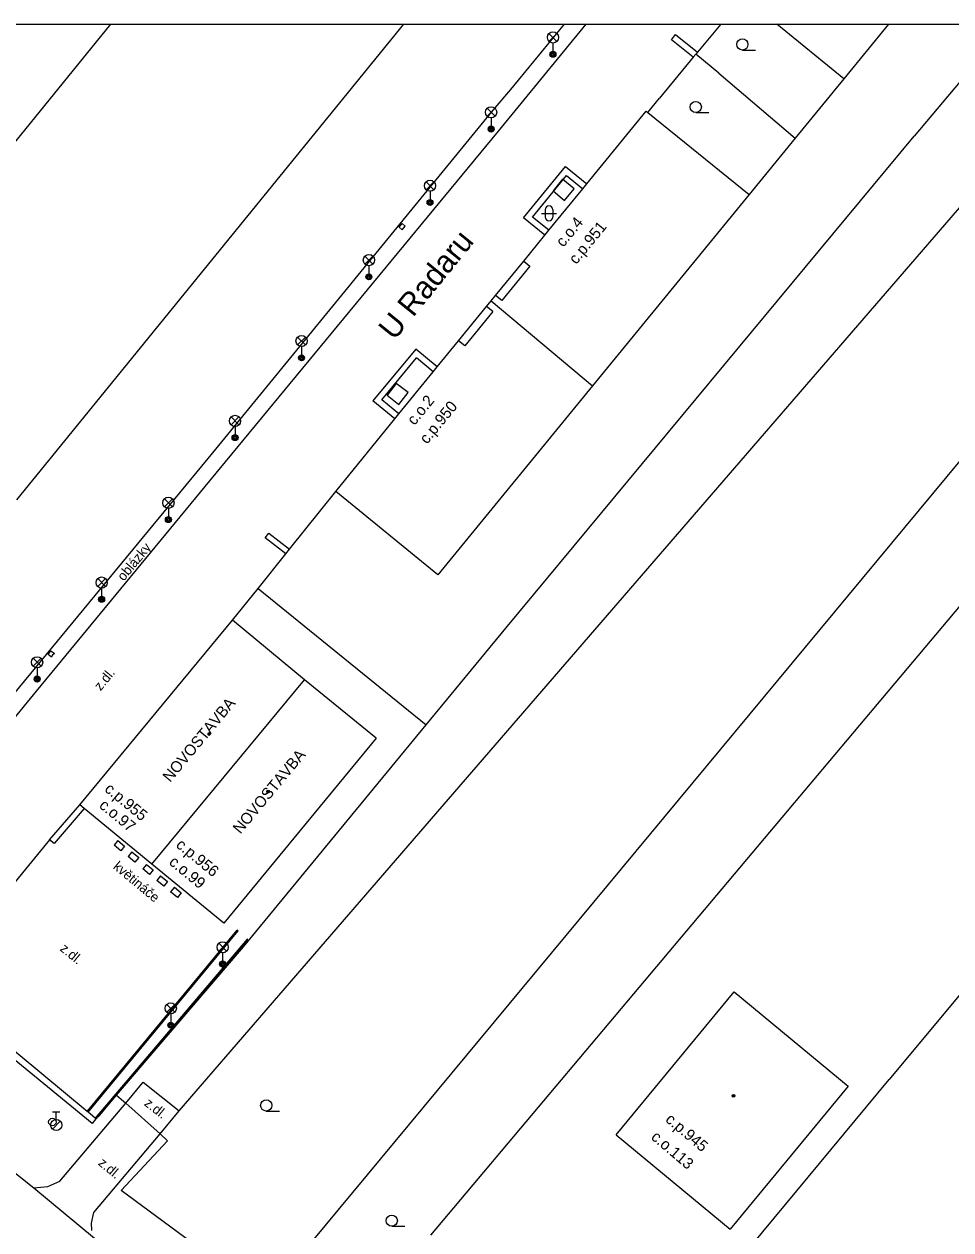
# Model space of a CAD drawing. Extents: x -594386 to -594050, y -1167541 to -1167175.
# Drawn here: x -594325.8 to -594263.8, y -1167256.2 to -1167175.4 of the extents above; entities that cross this region are included whole.
import ezdxf

# ---------------------------------------------------------------- set-up
doc = ezdxf.new("R2010")
doc.units = 0
for name, color, linetype in [('Level 24', 7, 'Continuous'), ('Level 25', 7, 'Continuous'), ('Level 26', 7, 'Continuous'), ('Level 28', 7, 'Continuous'), ('Level 33', 7, 'Continuous'), ('Level 36', 7, 'Continuous'), ('Level 39', 7, 'Continuous'), ('Level 41', 7, 'Continuous'), ('Vrstva 10', 7, 'Continuous'), ('Vrstva 11', 7, 'Continuous'), ('Vrstva 40', 7, 'Continuous'), ('Vrstva 42', 7, 'Continuous'), ('Vrstva 46', 7, 'Continuous'), ('Vrstva 5', 7, 'Continuous'), ('Vrstva 50', 7, 'Continuous'), ('Vrstva 51', 7, 'Continuous'), ('Vrstva 63', 7, 'Continuous'), ('Vrstva 7', 7, 'Continuous'), ('Vrstva 8', 7, 'Continuous')]:
    doc.layers.add(name, color=color, linetype=linetype)

msp = doc.modelspace()

# ---------------------------------------------------------------- linework, layer by layer
at = {"layer": 'Level 24'}
for points in [[(-594300.55, -1167189.2), (-594300.75, -1167189.02), (-594300.55, -1167188.79), (-594300.35, -1167188.97)], [(-594300.55, -1167189.2), (-594300.44, -1167189.07), (-594300.35, -1167188.97)], [(-594324.23, -1167217.65), (-594324.05, -1167217.41)], [(-594324.05, -1167217.41), (-594323.81, -1167217.58), (-594323.96, -1167217.72), (-594324.02, -1167217.83), (-594324.23, -1167217.65)]]:
    msp.add_lwpolyline(points, dxfattribs=at)
at = {"layer": 'Level 25'}
for points in [[(-594319.58, -1167230.12), (-594319.83, -1167230.43)], [(-594319.58, -1167230.12), (-594319.12, -1167230.5)], [(-594319.37, -1167230.81), (-594319.83, -1167230.43)], [(-594319.12, -1167230.5), (-594319.37, -1167230.81)], [(-594318.64, -1167230.88), (-594318.89, -1167231.19)], [(-594318.64, -1167230.88), (-594318.18, -1167231.26)], [(-594318.43, -1167231.57), (-594318.89, -1167231.19)], [(-594318.18, -1167231.26), (-594318.43, -1167231.57)], [(-594317.65, -1167231.71), (-594317.9, -1167232.02)], [(-594317.65, -1167231.71), (-594317.2, -1167232.08)], [(-594317.45, -1167232.39), (-594317.9, -1167232.02)], [(-594317.2, -1167232.08), (-594317.45, -1167232.39)], [(-594316.71, -1167232.49), (-594316.96, -1167232.8)], [(-594316.71, -1167232.49), (-594316.25, -1167232.87)], [(-594316.5, -1167233.18), (-594316.96, -1167232.8)], [(-594316.25, -1167232.87), (-594316.5, -1167233.18)], [(-594315.79, -1167233.25), (-594316.04, -1167233.56)], [(-594315.79, -1167233.25), (-594315.34, -1167233.62)], [(-594315.58, -1167233.94), (-594316.04, -1167233.56)], [(-594315.34, -1167233.62), (-594315.58, -1167233.94)]]:
    msp.add_lwpolyline(points, dxfattribs=at)
at = {"layer": 'Level 26'}
for points in [[(-594289.811, -1167185.826), (-594290.444, -1167186.601), (-594289.669, -1167187.234), (-594289.036, -1167186.459)], [(-594300.766, -1167200.902), (-594300.148, -1167200.116), (-594300.934, -1167199.498), (-594301.552, -1167200.284)]]:
    msp.add_lwpolyline(points, close=True, dxfattribs=at)
at = {"layer": 'Level 28'}
for p, q in [((-594323.95, -1167248.295), (-594323.45, -1167248.295)), ((-594323.7, -1167248.795), (-594323.7, -1167248.295)), ((-594323.958, -1167249.442), (-594323.428, -1167248.912))]:
    msp.add_line(p, q, dxfattribs=at)
for centre, radius in [((-594323.96, -1167248.97), 0.25), ((-594323.7, -1167249.17), 0.375)]:
    msp.add_circle(centre, radius, dxfattribs=at)
at = {"layer": 'Level 33'}
for p, q in [((-594290.715, -1167176.59), (-594290.185, -1167176.06)), ((-594290.715, -1167176.06), (-594290.185, -1167176.59)), ((-594290.45, -1167176.7), (-594290.45, -1167177.45)), ((-594294.855, -1167181.6), (-594294.325, -1167181.07)), ((-594294.855, -1167181.07), (-594294.325, -1167181.6)), ((-594294.59, -1167181.71), (-594294.59, -1167182.46)), ((-594298.945, -1167186.52), (-594298.415, -1167185.99)), ((-594298.945, -1167185.99), (-594298.415, -1167186.52)), ((-594298.68, -1167186.63), (-594298.68, -1167187.38)), ((-594303.035, -1167191.5), (-594302.505, -1167190.97)), ((-594303.035, -1167190.97), (-594302.505, -1167191.5)), ((-594302.77, -1167191.61), (-594302.77, -1167192.36)), ((-594307.545, -1167196.92), (-594307.015, -1167196.39)), ((-594307.545, -1167196.39), (-594307.015, -1167196.92)), ((-594307.28, -1167197.03), (-594307.28, -1167197.78)), ((-594311.995, -1167202.27), (-594311.465, -1167201.74)), ((-594311.995, -1167201.74), (-594311.465, -1167202.27)), ((-594311.73, -1167202.38), (-594311.73, -1167203.13)), ((-594316.455, -1167207.76), (-594315.925, -1167207.23)), ((-594316.455, -1167207.23), (-594315.925, -1167207.76)), ((-594316.19, -1167207.87), (-594316.19, -1167208.62)), ((-594320.925, -1167213.1), (-594320.395, -1167212.57)), ((-594320.925, -1167212.57), (-594320.395, -1167213.1)), ((-594320.66, -1167213.21), (-594320.66, -1167213.96)), ((-594325.245, -1167218.44), (-594324.715, -1167217.91)), ((-594325.245, -1167217.91), (-594324.715, -1167218.44)), ((-594324.98, -1167218.55), (-594324.98, -1167219.3)), ((-594312.825, -1167237.53), (-594312.295, -1167237)), ((-594312.825, -1167237), (-594312.295, -1167237.53)), ((-594312.56, -1167237.64), (-594312.56, -1167238.39)), ((-594316.295, -1167241.62), (-594315.765, -1167241.09)), ((-594316.295, -1167241.09), (-594315.765, -1167241.62)), ((-594316.03, -1167241.73), (-594316.03, -1167242.48))]:
    msp.add_line(p, q, dxfattribs=at)
for centre, radius in [((-594290.45, -1167176.325), 0.375), ((-594290.45, -1167177.45), 0.2), ((-594290.45, -1167177.45), 0.145), ((-594290.45, -1167177.45), 0.0876), ((-594294.59, -1167181.335), 0.375), ((-594294.59, -1167182.46), 0.2), ((-594294.59, -1167182.46), 0.145), ((-594294.59, -1167182.46), 0.0876), ((-594298.68, -1167186.255), 0.375), ((-594298.68, -1167187.38), 0.2), ((-594298.68, -1167187.38), 0.145), ((-594298.68, -1167187.38), 0.0876), ((-594302.77, -1167191.235), 0.375), ((-594302.77, -1167192.36), 0.2), ((-594302.77, -1167192.36), 0.145), ((-594302.77, -1167192.36), 0.0876), ((-594307.28, -1167196.655), 0.375), ((-594307.28, -1167197.78), 0.2), ((-594307.28, -1167197.78), 0.145), ((-594307.28, -1167197.78), 0.0876), ((-594311.73, -1167202.005), 0.375), ((-594311.73, -1167203.13), 0.2), ((-594311.73, -1167203.13), 0.145), ((-594311.73, -1167203.13), 0.0876), ((-594316.19, -1167207.495), 0.375), ((-594316.19, -1167208.62), 0.2), ((-594316.19, -1167208.62), 0.145), ((-594316.19, -1167208.62), 0.0876), ((-594320.66, -1167212.835), 0.375), ((-594320.66, -1167213.96), 0.2), ((-594320.66, -1167213.96), 0.145), ((-594320.66, -1167213.96), 0.0876), ((-594324.98, -1167218.175), 0.375), ((-594324.98, -1167219.3), 0.2), ((-594324.98, -1167219.3), 0.145), ((-594324.98, -1167219.3), 0.0876), ((-594312.56, -1167237.265), 0.375), ((-594312.56, -1167238.39), 0.2), ((-594312.56, -1167238.39), 0.145), ((-594312.56, -1167238.39), 0.0876), ((-594316.03, -1167241.355), 0.375), ((-594316.03, -1167242.48), 0.2), ((-594316.03, -1167242.48), 0.145), ((-594316.03, -1167242.48), 0.0876)]:
    msp.add_circle(centre, radius, dxfattribs=at)
at = {"layer": 'Level 36'}
for p, q in [((-594277.77, -1167177.165), (-594276.895, -1167177.165)), ((-594280.89, -1167181.355), (-594280.015, -1167181.355)), ((-594291.216, -1167188.106), (-594290.216, -1167188.106)), ((-594290.966, -1167187.856), (-594290.966, -1167188.356)), ((-594290.466, -1167187.856), (-594290.466, -1167188.356)), ((-594309.64, -1167248.235), (-594308.765, -1167248.235)), ((-594301.24, -1167255.955), (-594300.365, -1167255.955))]:
    msp.add_line(p, q, dxfattribs=at)
for centre in [(-594277.77, -1167176.79), (-594280.89, -1167180.98), (-594309.64, -1167247.86), (-594301.24, -1167255.58)]:
    msp.add_circle(centre, 0.375, dxfattribs=at)
for centre, start, end in [((-594290.716, -1167187.856), 0, 180), ((-594290.716, -1167188.356), 180, 0)]:
    msp.add_arc(centre, 0.25, start, end, dxfattribs=at)
at = {"layer": 'Level 39'}
for centre, radius in [((-594313.47, -1167222.98), 0.09), ((-594313.47, -1167222.98), 0.0398), ((-594309.52, -1167226.83), 0.09), ((-594309.52, -1167226.83), 0.0398), ((-594278.37, -1167247.22), 0.09), ((-594278.37, -1167247.22), 0.0398)]:
    msp.add_circle(centre, radius, dxfattribs=at)
at = {"layer": 'Vrstva 10'}
for points in [[(-594288.255, -1167175.43), (-594294.11, -1167182.6), (-594312.38, -1167204.76), (-594325.04, -1167220.12), (-594334.343, -1167231.486)], [(-594324.16, -1167230.06), (-594327.87, -1167234.59)], [(-594333.19, -1167246.94), (-594329.38, -1167250.07), (-594325.19, -1167253.37)], [(-594325.19, -1167253.37), (-594321.13, -1167256.75)]]:
    msp.add_lwpolyline(points, dxfattribs=at)
at = {"layer": 'Vrstva 11'}
msp.add_line((-594326.34, -1167207.29), (-594300.428, -1167175.43), dxfattribs=at)
for points in [[(-594279.34, -1167178.72), (-594274.23, -1167183.08)], [(-594270.97, -1167179.09), (-594274.23, -1167183.08)], [(-594274.23, -1167183.08), (-594277.31, -1167186.85)], [(-594290.73, -1167189.24), (-594291.83, -1167188.35), (-594289.55, -1167185.56), (-594288.46, -1167186.46)], [(-594315.46, -1167248.23), (-594261.8, -1167186.09)], [(-594301.9, -1167200.59), (-594299.58, -1167197.79)], [(-594298.46, -1167198.72), (-594299.58, -1167197.79)], [(-594300.76, -1167201.54), (-594301.9, -1167200.59)], [(-594310.19, -1167213.24), (-594298.94, -1167222.37)], [(-594321.62, -1167248.27), (-594311.58, -1167236.11)], [(-594321.56, -1167248.32), (-594311.52, -1167236.16)], [(-594310.92, -1167236.72), (-594321.09, -1167248.71)], [(-594310.88, -1167236.75), (-594321.04, -1167248.75)], [(-594311.52, -1167236.16), (-594311.58, -1167236.11)], [(-594310.88, -1167236.75), (-594310.92, -1167236.72)], [(-594319.05, -1167247.7), (-594317.89, -1167246.31), (-594315.46, -1167248.23)], [(-594325.19, -1167253.37), (-594324.26, -1167253.28), (-594323.46, -1167252.93), (-594319.05, -1167247.7)], [(-594316.75, -1167249.76), (-594315.46, -1167248.23)], [(-594321.32, -1167256.24), (-594321.33, -1167255.74), (-594321.18, -1167255.03), (-594316.75, -1167249.76)]]:
    msp.add_lwpolyline(points, dxfattribs=at)
at = {"layer": 'Vrstva 5'}
for p, q in [((-594270.97, -1167179.09), (-594275.458, -1167175.43)), ((-594267.986, -1167175.43), (-594270.97, -1167179.09))]:
    msp.add_line(p, q, dxfattribs=at)
for points in [[(-594288.19, -1167186.13), (-594284.22, -1167181.25)], [(-594284.22, -1167181.25), (-594284.1, -1167181.35)], [(-594284.1, -1167181.35), (-594277.31, -1167186.85)], [(-594290.73, -1167189.24), (-594288.46, -1167186.46)], [(-594288.46, -1167186.46), (-594288.19, -1167186.13)], [(-594277.31, -1167186.85), (-594287.81, -1167199.65)], [(-594292.41, -1167191.3), (-594291, -1167189.57)], [(-594291, -1167189.57), (-594290.73, -1167189.24)], [(-594292.41, -1167191.3), (-594291.99, -1167191.64), (-594293.87, -1167193.95), (-594294.29, -1167193.61)], [(-594294.29, -1167193.61), (-594292.41, -1167191.3)], [(-594294.9, -1167194.35), (-594294.58, -1167193.96)], [(-594294.58, -1167193.96), (-594294.29, -1167193.61)], [(-594294.58, -1167193.96), (-594287.81, -1167199.65)], [(-594296.77, -1167196.65), (-594294.9, -1167194.35)], [(-594294.48, -1167194.69), (-594296.35, -1167196.99), (-594296.77, -1167196.65)], [(-594294.48, -1167194.69), (-594294.9, -1167194.35)], [(-594298.19, -1167198.39), (-594296.77, -1167196.65)], [(-594300.76, -1167201.54), (-594298.46, -1167198.72)], [(-594298.46, -1167198.72), (-594298.19, -1167198.39)], [(-594287.81, -1167199.65), (-594298.15, -1167212.31), (-594304.99, -1167206.73)], [(-594304.99, -1167206.73), (-594301.04, -1167201.88)], [(-594301.04, -1167201.88), (-594300.76, -1167201.54)], [(-594322.11, -1167227.72), (-594311.89, -1167215.36)], [(-594307.08, -1167219.35), (-594311.89, -1167215.36)], [(-594317.29, -1167231.69), (-594307.08, -1167219.35)], [(-594302.29, -1167223.25), (-594307.08, -1167219.35)], [(-594302.29, -1167223.25), (-594312.49, -1167235.64), (-594317.29, -1167231.69)], [(-594321.82, -1167227.96), (-594322.11, -1167227.72)], [(-594317.29, -1167231.69), (-594321.82, -1167227.96)], [(-594286.21, -1167249.83), (-594278.31, -1167240.26), (-594270.69, -1167246.57)], [(-594270.69, -1167246.57), (-594278.59, -1167256.15)], [(-594286.21, -1167249.83), (-594278.59, -1167256.15)]]:
    msp.add_lwpolyline(points, dxfattribs=at)
at = {"layer": 'Vrstva 51'}
for p, q in [((-594334.03, -1167192.65), (-594320.033, -1167175.43)), ((-594230.477, -1167175.43), (-594298.65, -1167256.55))]:
    msp.add_line(p, q, dxfattribs=at)
for points in [[(-594306.69, -1167257.1), (-594253.6, -1167193.11)], [(-594228.81, -1167199.11), (-594267.95, -1167246.12)]]:
    msp.add_lwpolyline(points, dxfattribs=at)
at = {"layer": 'Vrstva 63'}
msp.add_lwpolyline([(-594386.36, -1167175.43), (-594049.75, -1167175.43), (-594049.75, -1167540.79), (-594386.36, -1167540.79)], close=True, dxfattribs=at)
at = {"layer": 'Vrstva 7'}
for p, q in [((-594289.706, -1167175.43), (-594293.29, -1167179.81)), ((-594279.218, -1167175.43), (-594280.77, -1167177.3)), ((-594259.985, -1167175.43), (-594266.27, -1167182.94))]:
    msp.add_line(p, q, dxfattribs=at)
for points in [[(-594281.06, -1167177.65), (-594282.52, -1167176.48), (-594282.24, -1167176.12), (-594280.77, -1167177.3)], [(-594281.06, -1167177.65), (-594283.31, -1167180.4)], [(-594280.89, -1167177.45), (-594281.06, -1167177.65)], [(-594280.77, -1167177.3), (-594280.89, -1167177.45)], [(-594279.34, -1167178.72), (-594280.89, -1167177.45)], [(-594293.29, -1167179.81), (-594294.47, -1167181.2), (-594313.23, -1167204.15), (-594335.22, -1167230.78)], [(-594298.94, -1167222.37), (-594293.61, -1167215.89), (-594266.27, -1167182.94)], [(-594291, -1167189.57), (-594292.42, -1167188.41), (-594289.61, -1167184.97), (-594288.19, -1167186.13)], [(-594299.63, -1167197.2), (-594302.5, -1167200.66)], [(-594298.19, -1167198.39), (-594299.63, -1167197.2)], [(-594301.04, -1167201.88), (-594302.5, -1167200.66)], [(-594308.09, -1167210.6), (-594304.99, -1167206.73)], [(-594308.33, -1167210.91), (-594309.71, -1167209.83), (-594309.47, -1167209.52), (-594308.09, -1167210.6)], [(-594310.19, -1167213.24), (-594308.33, -1167210.91)], [(-594308.33, -1167210.91), (-594308.09, -1167210.6)], [(-594311.89, -1167215.36), (-594310.19, -1167213.24)], [(-594311.17, -1167237.23), (-594298.94, -1167222.37)], [(-594324.16, -1167230.06), (-594322.11, -1167227.72)], [(-594321.82, -1167227.96), (-594323.83, -1167230.32)], [(-594323.83, -1167230.32), (-594324.16, -1167230.06)], [(-594319.66, -1167247.18), (-594311.17, -1167237.23)], [(-594321.04, -1167248.75), (-594321.29, -1167249.06), (-594332.27, -1167240.07)], [(-594321.62, -1167248.27), (-594327.73, -1167243.23)], [(-594288.88, -1167271.46), (-594281.83, -1167262.86), (-594267.95, -1167246.12)], [(-594321.04, -1167248.75), (-594320.79, -1167248.51), (-594319.66, -1167247.18)], [(-594321.56, -1167248.32), (-594321.62, -1167248.27)], [(-594321.09, -1167248.71), (-594321.56, -1167248.32)], [(-594321.04, -1167248.75), (-594321.09, -1167248.71)], [(-594309.49, -1167260.8), (-594310.92, -1167259.79), (-594319.35, -1167253.56), (-594316.26, -1167250.22)]]:
    msp.add_lwpolyline(points, dxfattribs=at)
at = {"layer": 'Vrstva 8'}
for points in [[(-594284.1, -1167181.35), (-594283.31, -1167180.4)], [(-594319.66, -1167247.18), (-594319.05, -1167247.7)], [(-594319.05, -1167247.7), (-594316.75, -1167249.76)], [(-594316.75, -1167249.76), (-594316.26, -1167250.22)]]:
    msp.add_lwpolyline(points, dxfattribs=at)

# ---------------------------------------------------------------- texts
at = {"layer": 'Level 41'}
for p in [(-594316.07, -1167226.26), (-594311.37, -1167229.72)]:
    msp.add_text('NOVOSTAVBA', height=0.75, rotation=50.32466, dxfattribs=at).set_placement(p)
at = {"layer": 'Vrstva 40'}
for s, rotation, p in [('oblázky', 50.45069, (-594319.18, -1167212.78)), ('z.dl.', 50.69991, (-594320.73, -1167220.13)), ('z.dl.', 320.47355, (-594323.5, -1167237.44)), ('z.dl.', 321.68692, (-594317.86, -1167247.81)), ('z.dl.', 320.20828, (-594320.94, -1167251.8))]:
    msp.add_text(s, height=0.65, rotation=rotation, dxfattribs=at).set_placement(p)
at = {"layer": 'Vrstva 42'}
msp.add_text('květináče', height=0.65, rotation=320.23748, dxfattribs=at).set_placement((-594319.94, -1167231.95))
at = {"layer": 'Vrstva 46'}
for s, rotation, p in [('c.o.4 ', 50.76, (-594289.754, -1167190.418)), ('c.p.951', 50.76, (-594288.89, -1167191.569)), ('c.o.2 ', 50.76, (-594299.716, -1167202.35)), ('c.p.950', 50.76, (-594298.879, -1167203.607)), ('c.p.955', 320.5, (-594320.521, -1167226.763)), ('c.o.97', 320.5, (-594320.882, -1167227.861)), ('c.p.956', 320.5, (-594315.742, -1167230.505)), ('c.o.99', 320.5, (-594316.206, -1167231.657)), ('c.p.945', 319.6583, (-594282.978, -1167248.887)), ('c.o.113', 319.6583, (-594283.938, -1167250.067))]:
    msp.add_text(s, height=0.75, rotation=rotation, dxfattribs=at).set_placement(p)
at = {"layer": 'Vrstva 50'}
msp.add_text('U Radaru', height=1.5, rotation=50.99646, dxfattribs=at).set_placement((-594301.076, -1167196.674))

doc.saveas('drawing.dxf')
